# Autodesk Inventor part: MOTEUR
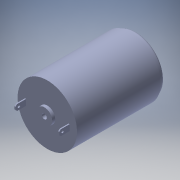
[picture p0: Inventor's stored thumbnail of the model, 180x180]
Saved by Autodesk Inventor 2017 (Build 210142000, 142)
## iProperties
Created: 2013-10
Part Number: MOTEUR
Material: Générique
Document SubType Name: Modeling
Designer: Bruno
Density: 1 g/cm^3
Appearance: Par défaut
Sending System: SolidWorks 2013
Last Author: christophe
Last Saved: 2014-02-15
Author: Bruno
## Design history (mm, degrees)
feature "Enlèv. mat.-Extru.3"
node "Solide1"
